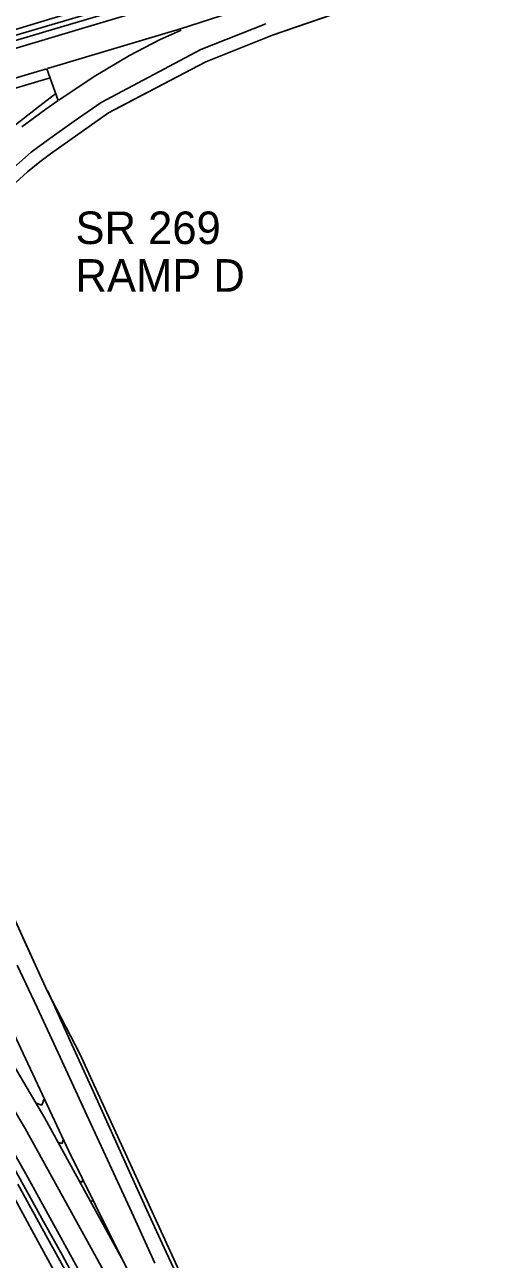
# Model space of a CAD drawing. Extents: x 1855721 to 1876784, y 662259 to 674089.
# Drawn here: x 1875933 to 1876189, y 668769 to 669452 of the extents above; entities that cross this region are included whole.
import ezdxf

# ---------------------------------------------------------------- set-up
doc = ezdxf.new("R2010")
doc.units = 0
for name, color, linetype in [('_CIVIL_CONSTRUCTION', 7, 'Continuous'), ('GE_X_Alignment_100_Bearings', 7, 'Continuous'), ('GE_X_Alignment_100_Cardinal_Points', 7, 'Continuous'), ('GE_X_Alignment_100_Curve_Data', 7, 'Continuous'), ('GE_X_Alignment_100_Distances', 7, 'Continuous'), ('GE_X_Alignment_100_Stations', 7, 'Continuous'), ('RD_P_GR_Rt', 7, 'Continuous'), ('SC_Scratch1', 7, 'Continuous')]:
    doc.layers.add(name, color=color, linetype=linetype)

msp = doc.modelspace()

# ---------------------------------------------------------------- linework, layer by layer
at = {"layer": '_CIVIL_CONSTRUCTION'}
msp.add_line((1875944.72, 669427.29), (1875951.07, 669409.77), dxfattribs=at)
for points in [[(1876065.75, 669452.15), (1876029.87, 669437.89), (1875974.71, 669408.51), (1875959.79, 669398.2), (1875946.34, 669388.63), (1875936.19, 669381.2), (1875921.46, 669368.3)], [(1875944.73, 669427.29), (1875939.6, 669425.76), (1875915.33, 669418.5), (1875869.39, 669405.09), (1875827.53, 669392.82), (1875786.54, 669380.59), (1875763.42, 669373.7), (1875729.79, 669363.76), (1875693.99, 669353.35), (1875653.79, 669341.59)], [(1875928.32, 668931.66), (1875939.42, 668908.14), (1875952.13, 668880.74), (1875968.04, 668846.29), (1875977.12, 668826.44), (1875992.78, 668792.51), (1876004.51, 668766.94)]]:
    msp.add_lwpolyline(points, dxfattribs=at)
at = {"layer": 'GE_X_Alignment_100_Bearings'}
msp.add_line((1876018.66, 669449.27), (1876177.88, 669501.05), dxfattribs=at)
msp.add_lwpolyline([(1875393.18, 669516.35), (1875460.82, 669452.24), (1875542.19, 669370.9), (1875595.16, 669313.1), (1875621.92, 669281.74), (1875667.43, 669226.81), (1875724.39, 669154.15), (1875781.24, 669077.33), (1875829.26, 669007.34), (1875885.44, 668921.11), (1875932.75, 668841.24), (1875975.99, 668762.9), (1876018.62, 668677.96), (1876059.41, 668589.69), (1876096.69, 668500.28), (1876133.1, 668404.85), (1876168.9, 668295.66)], dxfattribs=at)
at = {"layer": 'GE_X_Alignment_100_Cardinal_Points'}
msp.add_line((1875945.17, 669427.43), (1876018.66, 669449.27), dxfattribs=at)
for points in [[(1875951.34, 669409.97), (1875970.99, 669422.96), (1875990.44, 669434.51), (1876007.02, 669443.24), (1876018.93, 669448.65)], [(1875854.91, 668991.12), (1875895.74, 668928.06), (1875943.71, 668847.12), (1875986.44, 668769), (1875956.86, 668828.83), (1875925, 668897.01), (1875887.57, 668979.07), (1875877.16, 669003.88)]]:
    msp.add_lwpolyline(points, dxfattribs=at)
at = {"layer": 'GE_X_Alignment_100_Curve_Data'}
for points in [[(1876153.74, 669515.76), (1876130.48, 669508.91), (1876085.62, 669495.73), (1876058.36, 669487.8), (1876027.97, 669478.85), (1875995.52, 669469.26), (1875982.56, 669465.42), (1875955.53, 669457.37), (1875927.48, 669448.96), (1875901.1, 669441.03), (1875874.94, 669433.21), (1875846.59, 669424.81), (1875817.06, 669416.08), (1875760.37, 669399.34), (1875732.97, 669391.21), (1875700.91, 669381.7), (1875669.4, 669372.25), (1875635.17, 669361.7)], [(1875641.46, 669354.88), (1875673.63, 669364.21), (1875701.93, 669372.39), (1875756.34, 669388.06), (1875824.01, 669408.07), (1875852.37, 669416.45), (1875909.14, 669433.18), (1875964.18, 669449.52), (1876006.37, 669462.03), (1876053.96, 669476.16), (1876110.78, 669493.03), (1876165.11, 669509.13)], [(1875961.98, 668763.9), (1875933.08, 668816.23), (1875919.2, 668841.02), (1875881.01, 668905.64), (1875866.19, 668929.4), (1875826.37, 668991.09), (1875812.94, 669011.12), (1875775.03, 669065.75), (1875760.73, 669085.48), (1875721.92, 669138.27), (1875706.45, 669158.5), (1875658.48, 669219.48), (1875627.36, 669257.34), (1875609.67, 669278.66), (1875581.32, 669311.45), (1875545.48, 669350.06), (1875528.24, 669368.16), (1875464.77, 669431.52), (1875445.32, 669450.65)], [(1875442.31, 669430.05), (1875463.95, 669409.25), (1875485.17, 669388.12), (1875568.02, 669301.05), (1875591.61, 669275.08), (1875640.59, 669219.44), (1875656.86, 669199.97), (1875700.83, 669144.88), (1875716.99, 669123.89), (1875753.87, 669074.23), (1875768.23, 669054.56), (1875803.48, 669003.17), (1875820.28, 668978.53), (1875853.97, 668925.7), (1875879.49, 668884.01), (1875915.76, 668822.82), (1875938.77, 668781.09), (1875957.34, 668746.88)], [(1875930.87, 669395.16), (1875944.25, 669404.84), (1875951.11, 669409.66)]]:
    msp.add_lwpolyline(points, dxfattribs=at)
at = {"layer": 'GE_X_Alignment_100_Distances'}
msp.add_lwpolyline([(1875986.44, 668769), (1876029.09, 668683.95), (1876070.22, 668594.86), (1876107.71, 668505.95), (1876144.21, 668409.32), (1876189.3, 668271.3)], dxfattribs=at)
at = {"layer": 'GE_X_Alignment_100_Stations'}
for p, q in [((1875942.09, 668854.29), (1875938.86, 668855.31)), ((1875942.09, 668854.29), (1875943.2, 668857.8)), ((1875953.2, 668832.98), (1875953.88, 668835.12)), ((1875953.2, 668832.98), (1875951.14, 668833.64)), ((1875964.28, 668811.66), (1875962.86, 668812.11)), ((1875964.28, 668811.66), (1875964.7, 668812.97)), ((1875969.82, 668800.99), (1875968.76, 668801.33)), ((1875969.82, 668800.99), (1875970.13, 668801.97)), ((1875975.36, 668790.33), (1875974.65, 668790.55)), ((1875975.36, 668790.33), (1875975.57, 668790.98)), ((1875980.9, 668779.66), (1875980.55, 668779.78)), ((1875980.9, 668779.66), (1875981, 668779.99))]:
    msp.add_line(p, q, dxfattribs=at)
at = {"layer": 'RD_P_GR_Rt'}
for points in [[(1875927.62, 669364.33), (1875934.15, 669370.29), (1875940.81, 669375.76), (1875946.81, 669380.22), (1875978.84, 669402.85), (1876032.71, 669431.14), (1876069.44, 669445.79), (1876115.1, 669461.41)], [(1876028.91, 668738.52), (1875963.01, 668882.52), (1875945.02, 668917.41), (1875897.13, 669022.43)]]:
    msp.add_lwpolyline(points, dxfattribs=at)
at = {"layer": 'SC_Scratch1'}
for points in [[(1876156.8, 669513.89), (1876107.67, 669499.14), (1876038.39, 669478.6), (1875880.74, 669431.93), (1875722.42, 669385.1), (1875674.8, 669371.04), (1875637, 669359.72)], [(1875638.67, 669357.89), (1875668.47, 669366.58), (1875704.46, 669377.1), (1875747.69, 669389.76), (1875774.35, 669397.6), (1875857.28, 669422.13), (1875949.23, 669449.32), (1876078.09, 669487.57), (1876156.63, 669510.89), (1876160.58, 669512.07)], [(1876115.1, 669461.41), (1876082.21, 669450.16), (1876069.44, 669445.79), (1876032.71, 669431.14), (1875988.57, 669407.96), (1875978.84, 669402.85), (1875946.81, 669380.22), (1875940.81, 669375.76), (1875934.15, 669370.29), (1875927.62, 669364.33)], [(1875946.57, 669422.21), (1875929.23, 669417), (1875909.76, 669411.15), (1875885.39, 669403.84), (1875860.81, 669396.47), (1875833.41, 669388.26), (1875781.36, 669372.65), (1875746.53, 669362.71), (1875718.18, 669354.83), (1875687.3, 669347.93), (1875679.16, 669345.33)], [(1875925.71, 669394.99), (1875940.21, 669406.27), (1875949.68, 669413.6)], [(1875931.57, 668946.84), (1875945.02, 668917.41), (1875945.29, 668917.17), (1875957.71, 668889.87), (1875970.39, 668861.99), (1875990.38, 668817.35), (1876001.06, 668793.86), (1876010.72, 668772.91), (1876020.41, 668752.07)], [(1875926.82, 668819.09), (1875942.96, 668789.83), (1875953.33, 668771.05), (1875962.85, 668753.64)], [(1875958.52, 668756.4), (1875944.21, 668782.39), (1875928.74, 668810.51)]]:
    msp.add_lwpolyline(points, dxfattribs=at)

# ---------------------------------------------------------------- texts
for s, p in [('SR 269', (1875960.61, 669330.32)), ('RAMP D', (1875960.61, 669303.98))]:
    msp.add_text(s, height=18, dxfattribs=at).set_placement(p)

doc.saveas('drawing.dxf')
